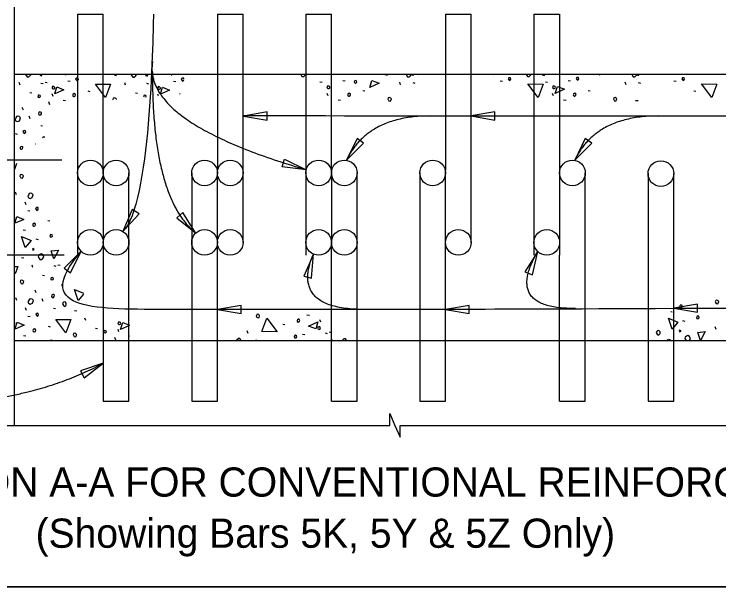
# Model space of a CAD drawing. Extents: x 0 to 20.6, y 0 to 13.
# Drawn here: x 1.553 to 4.642, y 0 to 2.51 of the extents above; entities that cross this region are included whole.
import ezdxf

# ---------------------------------------------------------------- set-up
doc = ezdxf.new("R2010")
doc.units = 0
for name, color, linetype in [('ActivePts-ConstElements', 7, 'Continuous'), ('BeamConc', 7, 'Continuous'), ('Dimension', 7, 'Continuous'), ('Miscellaneous', 7, 'Continuous'), ('Miscellaneous1', 7, 'Continuous'), ('Rebar', 7, 'Continuous'), ('Rebar_h', 7, 'Continuous')]:
    doc.layers.add(name, color=color, linetype=linetype)

msp = doc.modelspace()

# ---------------------------------------------------------------- linework, layer by layer
at = {"layer": 'ActivePts-ConstElements'}
msp.add_lwpolyline([(0, 0), (20.5253, 0), (20.5253, 12.9731), (0, 12.9731)], close=True, dxfattribs=at)
at = {"layer": 'BeamConc'}
for p, q in [((1.5537, 2.6243), (1.5537, 0.7075)), ((5.062, 2.2449), (1.5537, 2.2449)), ((5.062, 1.0783), (1.5537, 1.0783))]:
    msp.add_line(p, q, dxfattribs=at)
at = {"layer": 'Dimension'}
for p, q in [((1.7618, 1.8699), (1.3541, 1.8699)), ((1.772, 1.4533), (0.8208, 1.4533))]:
    msp.add_line(p, q, dxfattribs=at)
for points in [[(2.5583, 2.063), (2.6625, 2.0454), (2.6625, 2.0807)], [(3.5568, 2.0631), (3.6609, 2.0454), (3.6609, 2.0807)], [(3.0104, 1.8691), (3.0851, 1.9437), (3.0563, 1.9642)], [(4.0104, 1.869), (4.0851, 1.9436), (4.0563, 1.9641)], [(2.7385, 1.8736), (2.8335, 1.8275), (2.7286, 1.8398)], [(2.0296, 1.5571), (2.1009, 1.635), (2.0713, 1.6541)], [(2.349, 1.5512), (2.2933, 1.6409), (2.2669, 1.6175)], [(1.8469, 1.471), (1.772, 1.3965), (1.8007, 1.376)], [(2.865, 1.4582), (2.8231, 1.3612), (2.8574, 1.3529)], [(3.8484, 1.4696), (3.7922, 1.3801), (3.8248, 1.3666)], [(4.4442, 1.221), (4.5483, 1.2034), (4.5483, 1.2387)], [(2.4443, 1.2155), (2.5485, 1.1979), (2.5485, 1.2332)], [(3.4442, 1.2155), (3.5484, 1.1979), (3.5484, 1.2332)], [(1.9443, 0.9802), (1.8442, 0.9463), (1.861, 0.9153)]]:
    msp.add_lwpolyline(points, close=True, dxfattribs=at)
msp.add_lwpolyline([(1.4035, 0.7075), (3.2001, 0.7075), (3.2001, 0.7592), (3.2226, 0.7075), (3.2451, 0.6559), (3.2451, 0.7075), (5.2024, 0.7075)], dxfattribs=at)
for points, degree in [([(2.164, 2.5095), (2.1614, 2.383), (2.15, 1.6716), (2.03, 1.5574)], 3), ([(2.1601, 2.302), (2.1151, 2.0377), (2.8335, 1.8275)], 2), ([(2.1593, 2.254), (2.1583, 1.7028), (2.349, 1.5512)], 2), ([(5.2882, 2.0619), (4.0164, 2.0631), (3.5852, 2.0631), (2.5583, 2.0631)], 3), ([(3.3779, 2.0631), (3.1027, 2.0636), (3.0104, 1.8691)], 2), ([(4.3779, 2.0631), (4.1027, 2.0636), (4.0104, 1.869)], 2), ([(5.2957, 1.2227), (3.744, 1.2156), (3.3512, 1.2156), (2.139, 1.2156), (1.6304, 1.2156), (1.8469, 1.471)], 3), ([(3.0879, 1.2156), (2.7629, 1.2156), (2.865, 1.4582)], 2), ([(4.0134, 1.22), (3.7008, 1.2163), (3.8484, 1.4696)], 2), ([(1.1292, 0.8017), (1.6048, 0.7983), (1.9443, 0.9802)], 2)]:
    msp.add_open_spline(points, degree=degree, dxfattribs=at)
at = {"layer": 'Miscellaneous'}
for p, q in [((1.7812, 2.2417), (1.7803, 2.2441)), ((1.9927, 2.2423), (2.0027, 2.2405)), ((2.2443, 2.2405), (2.2436, 2.2424)), ((3.178, 2.2442), (3.188, 2.2424)), ((3.6569, 2.2424), (3.656, 2.2449)), ((3.8684, 2.243), (3.8784, 2.2412)), ((4.12, 2.2412), (4.1186, 2.2449)), ((1.5791, 2.1987), (1.575, 2.2099)), ((1.6705, 2.2075), (1.6799, 2.2052)), ((1.6887, 2.2116), (1.6981, 2.2093)), ((1.7883, 2.217), (1.7983, 2.2152)), ((2.0422, 2.1975), (2.0381, 2.2087)), ((2.1336, 2.2064), (2.143, 2.204)), ((2.1518, 2.2104), (2.1612, 2.2081)), ((2.2513, 2.2158), (2.2614, 2.214)), ((2.894, 2.2135), (2.9034, 2.2111)), ((2.9935, 2.2188), (3.0036, 2.2171)), ((3.2475, 2.1994), (3.2434, 2.2106)), ((3.3004, 2.2094), (3.3098, 2.2071)), ((3.684, 2.2177), (3.694, 2.2159)), ((3.8825, 2.2135), (3.8919, 2.2111)), ((3.982, 2.2188), (3.9921, 2.2171)), ((4.236, 2.1994), (4.2319, 2.2106)), ((4.2889, 2.2094), (4.2983, 2.2071)), ((4.4451, 2.2177), (4.4551, 2.2159)), ((1.6216, 2.1657), (1.6304, 2.1639)), ((1.8761, 2.1728), (1.8849, 2.171)), ((2.0847, 2.1645), (2.0935, 2.1627)), ((3.0813, 2.1746), (3.0902, 2.1729)), ((4.0698, 2.1746), (4.0787, 2.1729)), ((4.5329, 2.1735), (4.5418, 2.1717)), ((1.7241, 2.1492), (1.7199, 2.1604)), ((1.7682, 2.1321), (1.7788, 2.1309)), ((2.1861, 2.1509), (2.183, 2.1593)), ((2.9293, 2.1511), (2.9252, 2.1623)), ((2.9735, 2.134), (2.9841, 2.1328)), ((3.9178, 2.1511), (3.9137, 2.1623)), ((3.962, 2.134), (3.9726, 2.1328)), ((4.2772, 2.1316), (4.2879, 2.1305)), ((1.7099, 2.1127), (1.7052, 2.1245)), ((1.5939, 2.0885), (1.5892, 2.1003)), ((1.6239, 2.0502), (1.6192, 2.062)), ((1.6699, 2.0208), (1.6781, 2.0196)), ((1.5573, 1.986), (1.5673, 1.9842)), ((1.6451, 1.9418), (1.6469, 1.9415)), ((1.5639, 1.7181), (1.5592, 1.7299)), ((1.6058, 1.6739), (1.6016, 1.6851)), ((1.6128, 1.6492), (1.6228, 1.6474)), ((1.7006, 1.605), (1.7094, 1.6032)), ((1.5928, 1.5643), (1.6034, 1.5632)), ((1.6487, 1.5248), (1.6582, 1.5225)), ((1.5863, 1.4436), (1.5963, 1.4418)), ((1.6358, 1.3988), (1.6317, 1.41)), ((1.7272, 1.4076), (1.7366, 1.4053)), ((1.7454, 1.4117), (1.7548, 1.4094)), ((1.6782, 1.3658), (1.6871, 1.364)), ((1.6506, 1.2886), (1.6458, 1.3004)), ((1.7666, 1.3128), (1.7619, 1.3246)), ((1.5651, 1.255), (1.5604, 1.2668)), ((1.6806, 1.2503), (1.6759, 1.2621)), ((1.6069, 1.2108), (1.6028, 1.222)), ((1.7265, 1.2209), (1.7348, 1.2197)), ((1.8185, 1.2114), (1.8285, 1.2097)), ((4.4316, 1.2062), (4.438, 1.2055)), ((1.614, 1.1861), (1.624, 1.1843)), ((1.868, 1.1667), (1.8638, 1.1779)), ((2.8474, 1.1889), (2.8368, 1.1901)), ((2.7396, 1.1483), (2.7307, 1.15)), ((2.8916, 1.1718), (2.8957, 1.1606)), ((4.4834, 1.1672), (4.4928, 1.1648)), ((1.7018, 1.1419), (1.7106, 1.1401)), ((1.9104, 1.1337), (1.9192, 1.1319)), ((2.0129, 1.1172), (2.0087, 1.1284)), ((2.5734, 1.1235), (2.5775, 1.1123)), ((2.9452, 1.1135), (2.9357, 1.1158)), ((4.6307, 1.1283), (4.626, 1.1401)), ((1.5939, 1.1012), (1.6046, 1.1001)), ((1.9987, 1.0807), (1.994, 1.0924)), ((2.057, 1.1001), (2.0596, 1.0998)), ((2.8274, 1.1041), (2.8174, 1.1058)), ((2.9269, 1.1094), (2.9175, 1.1118)), ((4.421, 1.0859), (4.431, 1.0841)), ((2.6229, 1.0787), (2.6129, 1.0805)), ((2.8344, 1.0794), (2.8349, 1.078))]:
    msp.add_line(p, q, dxfattribs=at)
for points in [[(1.6032, 2.2448), (1.6098, 2.234), (1.6174, 2.2346), (1.6204, 2.2376), (1.6269, 2.2441), (1.6266, 2.2447)], [(1.6704, 2.237), (1.668, 2.2445)], [(1.6743, 2.2445), (1.6704, 2.237)], [(1.8254, 2.2211), (1.8289, 2.2176), (1.8325, 2.2199), (1.8348, 2.2234), (1.8336, 2.2293), (1.8307, 2.2299), (1.8266, 2.2293), (1.823, 2.2258), (1.8254, 2.2211)], [(2.0665, 2.2431), (2.0729, 2.2329), (2.0805, 2.2335), (2.0835, 2.2364), (2.09, 2.2429), (2.0899, 2.243)], [(2.1335, 2.2358), (2.1312, 2.2429)], [(2.1372, 2.2428), (2.1335, 2.2358)], [(2.2976, 2.2239), (2.2967, 2.2282), (2.2938, 2.2287), (2.2896, 2.2282), (2.2861, 2.2246), (2.2885, 2.2199)], [(2.8095, 2.2449), (2.8151, 2.2359), (2.8227, 2.2365), (2.8257, 2.2395), (2.8312, 2.2449)], [(3.2718, 2.2449), (3.2781, 2.2348), (3.2858, 2.2353), (3.2888, 2.2383), (3.2952, 2.2448), (3.2952, 2.2449)], [(3.3003, 2.2388), (3.2984, 2.2449)], [(3.3035, 2.2449), (3.3003, 2.2388)], [(3.3167, 2.2441), (3.3164, 2.2449)], [(3.3225, 2.2449), (3.3212, 2.2424)], [(3.7211, 2.2218), (3.7246, 2.2183), (3.7282, 2.2206), (3.7305, 2.2241), (3.7293, 2.23), (3.7264, 2.2306), (3.7223, 2.23), (3.7187, 2.2265), (3.7211, 2.2218)], [(3.798, 2.2449), (3.8036, 2.2359), (3.8112, 2.2365), (3.8142, 2.2395), (3.8197, 2.2449)], [(4.0192, 2.223), (4.0227, 2.2194), (4.0262, 2.2218), (4.0286, 2.2253), (4.0274, 2.2312), (4.0245, 2.2318), (4.0203, 2.2312), (4.0168, 2.2277), (4.0192, 2.223)], [(4.2603, 2.2449), (4.2666, 2.2348), (4.2743, 2.2353), (4.2773, 2.2383), (4.2837, 2.2448), (4.2837, 2.2449)], [(4.2888, 2.2388), (4.2869, 2.2449)], [(4.292, 2.2449), (4.2888, 2.2388)], [(4.4822, 2.2218), (4.4858, 2.2183), (4.4893, 2.2206), (4.4917, 2.2241), (4.4905, 2.23), (4.4875, 2.2306), (4.4834, 2.23), (4.4799, 2.2265), (4.4822, 2.2218)], [(1.7229, 2.1822), (1.727, 2.1816), (1.7311, 2.1833), (1.7323, 2.1869), (1.7305, 2.1898), (1.727, 2.1922), (1.7229, 2.1939), (1.7205, 2.1892), (1.7194, 2.1857), (1.7229, 2.1822)], [(1.9544, 2.1439), (1.9096, 2.2028), (1.9762, 2.2022), (1.9544, 2.1439)], [(2.2885, 2.2199), (2.292, 2.2164), (2.2955, 2.2187), (2.2969, 2.2208)], [(2.9282, 2.184), (2.9323, 2.1834), (2.9364, 2.1852), (2.9376, 2.1888), (2.9358, 2.1917), (2.9323, 2.1941), (2.9282, 2.1958), (2.9258, 2.1911), (2.9246, 2.1876), (2.9282, 2.184)], [(3.0458, 2.2092), (3.0494, 2.2057), (3.0529, 2.2081), (3.0553, 2.2116), (3.0541, 2.2175), (3.0512, 2.2181), (3.047, 2.2175), (3.0435, 2.2139), (3.0458, 2.2092)], [(3.1125, 2.1882), (3.1219, 2.2188), (3.1531, 2.2065), (3.1125, 2.1882)], [(3.8501, 2.1446), (3.8054, 2.2035), (3.8719, 2.2029), (3.8501, 2.1446)], [(3.9167, 2.184), (3.9208, 2.1834), (3.9249, 2.1852), (3.9261, 2.1888), (3.9243, 2.1917), (3.9208, 2.1941), (3.9167, 2.1958), (3.9143, 2.1911), (3.9131, 2.1876), (3.9167, 2.184)], [(4.6113, 2.1446), (4.5665, 2.2035), (4.6331, 2.2029), (4.6113, 2.1446)], [(1.7311, 2.1598), (1.7405, 2.1904), (1.7718, 2.1781), (1.7311, 2.1598)], [(2.186, 2.181), (2.1901, 2.1804), (2.1942, 2.1822), (2.1954, 2.1857), (2.1936, 2.1886), (2.1901, 2.191), (2.186, 2.1928), (2.1836, 2.1881), (2.1824, 2.1845), (2.186, 2.181)], [(2.1942, 2.1586), (2.2036, 2.1893), (2.2348, 2.1769), (2.1942, 2.1586)], [(3.0189, 2.1499), (3.0212, 2.1499), (3.0259, 2.1523), (3.0277, 2.1576), (3.0271, 2.1605), (3.0224, 2.1629), (3.0165, 2.1593), (3.0153, 2.1558), (3.0165, 2.1523), (3.0189, 2.1499)], [(3.9249, 2.1617), (3.9343, 2.1923), (3.9655, 2.18), (3.9249, 2.1617)], [(4.0074, 2.1499), (4.0097, 2.1499), (4.0144, 2.1523), (4.0162, 2.1576), (4.0156, 2.1605), (4.0109, 2.1629), (4.005, 2.1593), (4.0038, 2.1558), (4.005, 2.1523), (4.0074, 2.1499)], [(1.6575, 2.1463), (1.664, 2.1445), (1.6681, 2.1474), (1.6687, 2.1516), (1.6675, 2.1527), (1.6628, 2.1551), (1.6587, 2.1545), (1.6581, 2.1504), (1.6575, 2.1463)], [(1.8136, 2.148), (1.816, 2.148), (1.8207, 2.1504), (1.8224, 2.1557), (1.8218, 2.1586), (1.8171, 2.161), (1.8112, 2.1574), (1.8101, 2.1539), (1.8112, 2.1504), (1.8136, 2.148)], [(2.0011, 2.1348), (2.0016, 2.1368), (1.9986, 2.1398), (1.9933, 2.1427), (1.988, 2.1409), (1.9862, 2.1356), (1.9873, 2.1336)], [(2.131, 2.1461), (2.1312, 2.1463), (2.1318, 2.1504), (2.1306, 2.1516), (2.1259, 2.1539), (2.1218, 2.1533), (2.1212, 2.1492), (2.1206, 2.1452)], [(2.2815, 2.1592), (2.2802, 2.1598), (2.2788, 2.1589)], [(3.1927, 2.1352), (3.1957, 2.1299), (3.2027, 2.1287), (3.2057, 2.134), (3.2068, 2.1387), (3.2039, 2.1416), (3.1986, 2.1446), (3.1933, 2.1428), (3.1915, 2.1375), (3.1927, 2.1352)], [(4.1812, 2.1352), (4.1842, 2.1299), (4.1912, 2.1287), (4.1942, 2.134), (4.1953, 2.1387), (4.1924, 2.1416), (4.1871, 2.1446), (4.1818, 2.1428), (4.18, 2.1375), (4.1812, 2.1352)], [(1.6604, 2.0726), (1.6634, 2.0673), (1.6699, 2.0679), (1.6728, 2.072), (1.6734, 2.0785), (1.6693, 2.0803), (1.6663, 2.0809), (1.6628, 2.0797), (1.6616, 2.0785), (1.6604, 2.0726)], [(1.5597, 2.0425), (1.5674, 2.0384), (1.5774, 2.0425), (1.5815, 2.0549), (1.5756, 2.0608), (1.5679, 2.0626), (1.5644, 2.0602), (1.5603, 2.0537), (1.5573, 2.0484), (1.5597, 2.0425)], [(1.5944, 1.9901), (1.598, 1.9866), (1.6015, 1.989), (1.6039, 1.9925), (1.6027, 1.9984), (1.5997, 1.999), (1.5956, 1.9984), (1.5921, 1.9948), (1.5944, 1.9901)], [(1.682, 1.9675), (1.6787, 1.9719), (1.6877, 1.9718)], [(1.5826, 1.9171), (1.585, 1.9171), (1.5897, 1.9194), (1.5915, 1.9247), (1.5909, 1.9277), (1.5862, 1.93), (1.5803, 1.9265), (1.5791, 1.923), (1.5803, 1.9194), (1.5826, 1.9171)], [(1.5537, 1.8667), (1.5569, 1.8667)], [(1.5641, 1.8544), (1.5543, 1.8282)], [(1.5798, 1.7976), (1.5828, 1.7923), (1.5899, 1.7912), (1.5928, 1.7965), (1.594, 1.8012), (1.591, 1.8041), (1.5857, 1.8071), (1.5804, 1.8053), (1.5787, 1.8), (1.5798, 1.7976)], [(1.6152, 1.7057), (1.6229, 1.7016), (1.6329, 1.7057), (1.637, 1.7181), (1.6311, 1.724), (1.6234, 1.7257), (1.6199, 1.7234), (1.6158, 1.7169), (1.6128, 1.7116), (1.6152, 1.7057)], [(1.6499, 1.6533), (1.6535, 1.6498), (1.657, 1.6521), (1.6594, 1.6557), (1.6582, 1.6616), (1.6552, 1.6621), (1.6511, 1.6616), (1.6476, 1.658), (1.6499, 1.6533)], [(1.5576, 1.5985), (1.5651, 1.6227), (1.5963, 1.6103), (1.5577, 1.593)], [(1.6381, 1.5802), (1.6405, 1.5802), (1.6452, 1.5826), (1.647, 1.5879), (1.6464, 1.5908), (1.6417, 1.5932), (1.6358, 1.5897), (1.6346, 1.5861), (1.6358, 1.5826), (1.6381, 1.5802)], [(1.6022, 1.4866), (1.5863, 1.5355), (1.6282, 1.5172), (1.6022, 1.4866)], [(1.7112, 1.5331), (1.7183, 1.5331), (1.7218, 1.5366), (1.72, 1.5431), (1.7124, 1.5437), (1.7112, 1.5402), (1.7094, 1.5372), (1.7112, 1.5331), (1.71, 1.5343)], [(1.6352, 1.4748), (1.6417, 1.4777), (1.6394, 1.4801), (1.6352, 1.4819), (1.6335, 1.4777), (1.6352, 1.4748)], [(1.6588, 1.4465), (1.6665, 1.4341), (1.6741, 1.4347), (1.6771, 1.4377), (1.6835, 1.4442), (1.6794, 1.4542), (1.6712, 1.4589), (1.6653, 1.4565), (1.6606, 1.4518), (1.6588, 1.4465)], [(1.7271, 1.4371), (1.7159, 1.4718), (1.7472, 1.4759), (1.7271, 1.4371)], [(1.5579, 1.4036), (1.5698, 1.4035), (1.5579, 1.3717)], [(1.581, 1.3346), (1.584, 1.3293), (1.591, 1.3281), (1.594, 1.3334), (1.5952, 1.3381), (1.5922, 1.341), (1.5869, 1.344), (1.5816, 1.3422), (1.5798, 1.3369), (1.581, 1.3346)], [(1.7142, 1.3463), (1.7207, 1.3446), (1.7248, 1.3475), (1.7254, 1.3516), (1.7242, 1.3528), (1.7195, 1.3552), (1.7154, 1.3546), (1.7148, 1.3505), (1.7142, 1.3463)], [(1.8344, 1.2545), (1.8185, 1.3034), (1.8571, 1.2865)], [(1.7171, 1.2727), (1.72, 1.2674), (1.7265, 1.268), (1.7295, 1.2721), (1.7301, 1.2786), (1.7259, 1.2804), (1.723, 1.281), (1.7195, 1.2798), (1.7183, 1.2786), (1.7171, 1.2727)], [(1.8577, 1.282), (1.8344, 1.2545)], [(1.6164, 1.2426), (1.624, 1.2385), (1.6341, 1.2426), (1.6382, 1.255), (1.6323, 1.2609), (1.6246, 1.2627), (1.6211, 1.2603), (1.617, 1.2538), (1.614, 1.2485), (1.6164, 1.2426)], [(1.7654, 1.2397), (1.769, 1.2327), (1.7748, 1.2291), (1.7796, 1.2327), (1.7819, 1.2362), (1.7819, 1.2433), (1.7766, 1.2486), (1.7701, 1.248), (1.7672, 1.245), (1.7654, 1.2397)], [(4.6277, 1.2467), (4.6306, 1.2414), (4.6377, 1.2402), (4.6406, 1.2455), (4.6418, 1.2502), (4.6389, 1.2531), (4.6336, 1.2561), (4.6283, 1.2543), (4.6265, 1.249), (4.6277, 1.2467)], [(4.4728, 1.2226), (4.4752, 1.2226), (4.4799, 1.2249), (4.4817, 1.2302), (4.4811, 1.2332), (4.4763, 1.2355), (4.4705, 1.232), (4.4693, 1.2285), (4.4705, 1.2249), (4.4728, 1.2226)], [(1.6511, 1.1902), (1.6546, 1.1867), (1.6582, 1.189), (1.6605, 1.1926), (1.6594, 1.1985), (1.6564, 1.1991), (1.6523, 1.1985), (1.6487, 1.1949), (1.6511, 1.1902)], [(2.6282, 1.1877), (2.6253, 1.193), (2.6182, 1.1942), (2.6152, 1.1889), (2.6141, 1.1842), (2.617, 1.1813), (2.6223, 1.1783), (2.6276, 1.1801), (2.6294, 1.1854), (2.6282, 1.1877)], [(2.6612, 1.1771), (2.706, 1.1182), (2.6394, 1.1188), (2.6612, 1.1771)], [(4.4369, 1.1289), (4.421, 1.1778), (4.4628, 1.1595), (4.4369, 1.1289)], [(4.5459, 1.1754), (4.553, 1.1754), (4.5565, 1.179), (4.5547, 1.1854), (4.5471, 1.186), (4.5459, 1.1825), (4.5441, 1.1795), (4.5459, 1.1754), (4.5447, 1.1766)], [(1.5579, 1.1325), (1.5663, 1.1596), (1.5975, 1.1472), (1.5579, 1.1294)], [(1.5579, 1.1557), (1.558, 1.156), (1.5579, 1.1562)], [(1.7802, 1.113), (1.7354, 1.172), (1.802, 1.1714), (1.7802, 1.113)], [(2.0117, 1.1501), (2.0158, 1.1495), (2.0199, 1.1513), (2.0211, 1.1548), (2.0194, 1.1578), (2.0158, 1.1601), (2.0117, 1.1619), (2.0093, 1.1572), (2.0082, 1.1537), (2.0117, 1.1501)], [(2.0199, 1.1278), (2.0293, 1.1584), (2.0596, 1.1464)], [(2.0596, 1.1456), (2.0199, 1.1278)], [(2.802, 1.173), (2.7997, 1.173), (2.795, 1.1707), (2.7932, 1.1653), (2.7938, 1.1624), (2.7985, 1.16), (2.8044, 1.1636), (2.8056, 1.1671), (2.8044, 1.1707), (2.802, 1.173)], [(2.8845, 1.1612), (2.8751, 1.1306), (2.8439, 1.143), (2.8845, 1.1612)], [(1.6393, 1.1172), (1.6417, 1.1172), (1.6464, 1.1195), (1.6482, 1.1248), (1.6476, 1.1278), (1.6429, 1.1301), (1.637, 1.1266), (1.6358, 1.1231), (1.637, 1.1195), (1.6393, 1.1172)], [(1.9463, 1.1142), (1.9528, 1.1124), (1.9569, 1.1154), (1.9575, 1.1195), (1.9563, 1.1207), (1.9516, 1.1231), (1.9475, 1.1225), (1.9469, 1.1183), (1.9463, 1.1142)], [(2.8927, 1.1389), (2.8886, 1.1395), (2.8845, 1.1377), (2.8833, 1.1342), (2.8851, 1.1312), (2.8886, 1.1288), (2.8927, 1.1271), (2.8951, 1.1318), (2.8963, 1.1353), (2.8927, 1.1389)], [(4.368, 1.1142), (4.3715, 1.1071), (4.3774, 1.1036), (4.3821, 1.1071), (4.3845, 1.1106), (4.3845, 1.1177), (4.3792, 1.123), (4.3727, 1.1224), (4.3697, 1.1195), (4.368, 1.1142)], [(4.4699, 1.1171), (4.4764, 1.1201), (4.474, 1.1224), (4.4699, 1.1242), (4.4681, 1.1201), (4.4699, 1.1171)], [(4.5618, 1.0794), (4.5506, 1.1141), (4.5818, 1.1183), (4.5618, 1.0794)], [(1.8131, 1.1024), (1.8161, 1.0971), (1.8232, 1.0959), (1.8261, 1.1012), (1.8273, 1.106), (1.8243, 1.1089), (1.819, 1.1119), (1.8137, 1.1101), (1.812, 1.1048), (1.8131, 1.1024)], [(2.5491, 1.078), (2.5428, 1.0882), (2.5351, 1.0876), (2.5322, 1.0846), (2.5257, 1.0781), (2.5258, 1.078)], [(2.7903, 1.0999), (2.7867, 1.1035), (2.7832, 1.1011), (2.7808, 1.0976), (2.782, 1.0917), (2.785, 1.0911), (2.7891, 1.0917), (2.7926, 1.0952), (2.7903, 1.0999)], [(2.942, 1.078), (2.9452, 1.0841)], [(2.9452, 1.0841), (2.9472, 1.078)], [(3.0114, 1.078), (3.0058, 1.087), (2.9982, 1.0864), (2.9952, 1.0834), (2.9898, 1.078)], [(4.4167, 1.0835), (4.414, 1.0783)], [(4.5111, 1.0794), (4.5117, 1.08), (4.5182, 1.0865), (4.5141, 1.0965), (4.5058, 1.1012), (4.5, 1.0989), (4.4952, 1.0941), (4.4935, 1.0888)], [(4.4935, 1.0888), (4.4993, 1.0794)], [(1.7221, 1.0768), (1.7212, 1.08), (1.7136, 1.0806), (1.7124, 1.0771), (1.7122, 1.0768)], [(2.4784, 1.078), (2.4797, 1.0805)], [(2.4842, 1.0788), (2.4845, 1.078)]]:
    msp.add_lwpolyline(points, dxfattribs=at)
at = {"layer": 'Miscellaneous1'}
msp.add_lwpolyline([(0, 12.9731), (20.5253, 12.9731), (20.5253, 0), (0, 0)], close=True, dxfattribs=at)
at = {"layer": 'Rebar'}
for centre in [(1.888, 1.8137), (2.0005, 1.8137), (2.388, 1.8137), (2.5006, 1.8137), (2.888, 1.8137), (3.0005, 1.8137), (3.3881, 1.8137), (4.0005, 1.8137), (4.3881, 1.8106), (4.3881, 1.8106), (1.888, 1.5095), (2.0005, 1.5095), (2.388, 1.5095), (2.5005, 1.5095), (2.5005, 1.5095), (2.888, 1.5095), (3.0005, 1.5095), (3.5006, 1.5095), (3.888, 1.5095)]:
    msp.add_circle(centre, 0.0563, dxfattribs=at)
at = {"layer": 'Rebar_h'}
for p, q in [((1.8318, 2.5095), (1.9443, 2.5095)), ((2.4443, 2.5095), (2.5568, 2.5095)), ((2.8318, 2.5095), (2.9443, 2.5095)), ((3.4444, 2.5095), (3.5568, 2.5095)), ((3.8318, 2.5095), (3.9443, 2.5095)), ((1.9443, 0.8137), (2.0568, 0.8137)), ((2.3318, 0.8137), (2.4443, 0.8137)), ((2.9443, 0.8137), (3.0568, 0.8137)), ((3.3318, 0.8137), (3.4443, 0.8137)), ((3.9443, 0.8137), (4.0568, 0.8137)), ((4.3318, 0.8137), (4.4443, 0.8137))]:
    msp.add_line(p, q, dxfattribs=at)
for points in [[(1.8318, 2.5095), (1.8318, 1.4533)], [(1.9443, 1.8179), (1.9443, 2.5095)], [(2.4443, 2.5095), (2.4443, 1.8283)], [(2.5568, 1.5095), (2.5568, 2.5095)], [(2.8318, 2.5095), (2.8318, 1.4533)], [(2.9443, 1.8179), (2.9443, 2.5095)], [(3.4444, 2.5095), (3.4444, 1.8252)], [(3.5568, 1.5095), (3.5568, 2.5095)], [(3.8318, 2.5095), (3.8318, 1.4533)], [(3.9443, 2.5095), (3.9443, 1.4533)], [(2.4443, 0.8137), (2.4443, 1.8283)], [(3.4443, 0.8137), (3.4443, 1.8252)], [(1.9443, 1.8179), (1.9443, 1.4949)], [(2.0568, 0.8137), (2.0568, 1.8137)], [(2.3318, 1.8137), (2.3318, 0.8137)], [(2.9443, 1.8179), (2.9443, 1.4949)], [(3.0568, 0.8137), (3.0568, 1.8137)], [(3.3318, 1.8137), (3.3318, 0.8137)], [(4.0568, 0.8137), (4.0568, 1.8137)], [(4.3318, 1.8106), (4.3318, 0.8137)], [(4.4443, 0.8137), (4.4443, 1.8106)], [(1.9443, 1.4949), (1.9443, 0.8137)], [(2.9443, 0.8137), (2.9443, 1.4949)], [(3.9443, 0.8137), (3.9443, 1.4533)]]:
    msp.add_lwpolyline(points, dxfattribs=at)

# ---------------------------------------------------------------- texts
at = {"layer": 'Dimension'}
for s, p in [('SECTION A-A FOR CONVENTIONAL REINFORCING', (0.8992, 0.3954)), ('(Showing Bars 5K, 5Y & 5Z Only)', (1.6474, 0.1714))]:
    msp.add_text(s, height=0.128, dxfattribs=at).set_placement(p)

doc.saveas('drawing.dxf')
